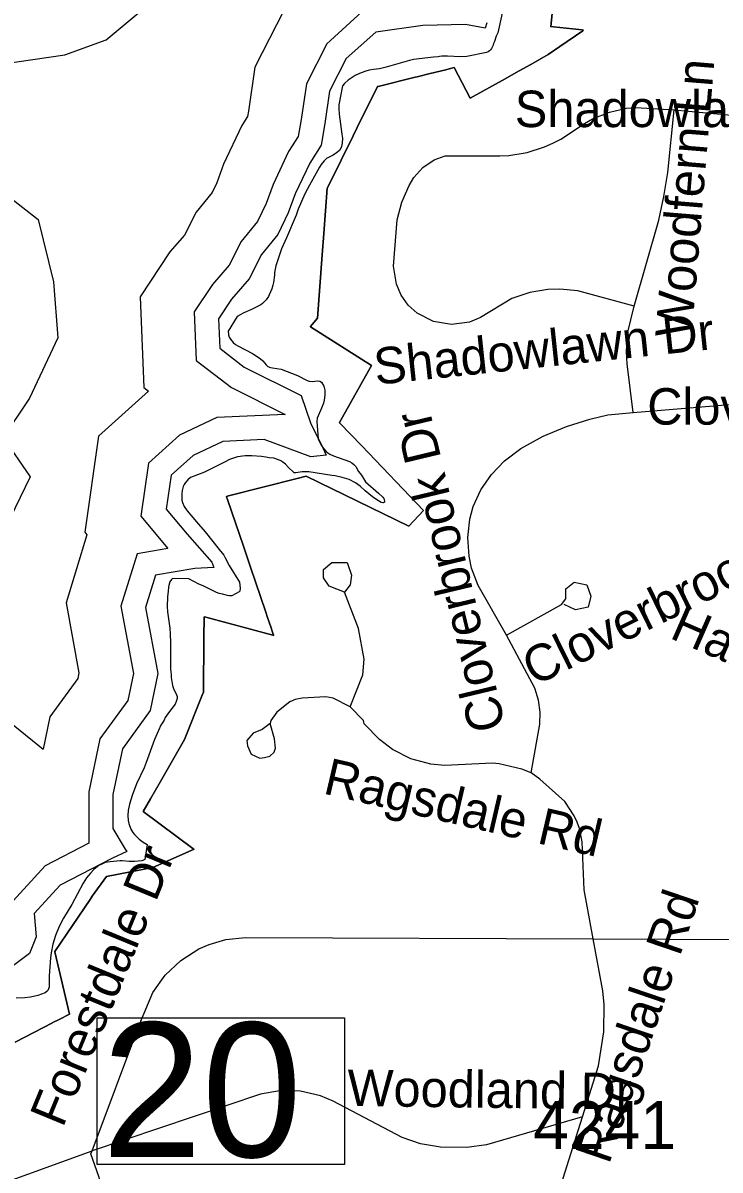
# Model space of a CAD drawing. Extents: x 1662474 to 1856135, y 779280 to 917889.
# Drawn here: x 1721124 to 1722940, y 819694 to 822681 of the extents above; entities that cross this region are included whole.
import ezdxf

# ---------------------------------------------------------------- set-up
doc = ezdxf.new("R2010")
doc.units = 0
for name, color, linetype in [('Exist Boundary Political City Limit New', 7, 'Continuous'), ('Exist Hydrographic Buffer Line', 7, 'Continuous'), ('Exist Hydrographic Lake Shore', 7, 'Continuous'), ('Exist Road Non-System Type 51', 7, 'Continuous'), ('Exist Road Non-System Type 51 Label', 7, 'Continuous'), ('Exist Road Secondary Structure Standard Bridge Number Label', 7, 'Continuous'), ('Exist Road Secondary Type 51 Number Label', 7, 'Continuous'), ('Map Preparation Boundary City Limit Buffer Line', 7, 'Continuous')]:
    doc.layers.add(name, color=color, linetype=linetype)

msp = doc.modelspace()

# ---------------------------------------------------------------- linework, layer by layer
at = {"layer": 'Exist Boundary Political City Limit New'}
for points in [[(1722511.6, 822791.3), (1722499.1, 822672.2), (1722499, 822671.6), (1722506.8, 822670.7), (1722556, 822665.6), (1722581, 822663), (1722584.5, 822662.3), (1722582.4, 822660.8), (1722523, 822619.5), (1722492.9, 822598.5), (1722447, 822572.9), (1722445.4, 822572), (1722409.2, 822551.9), (1722380.8, 822535.8), (1722289.6, 822484.8), (1722248.1, 822564.9), (1722234.4, 822561.4), (1722226.4, 822559.4), (1722184.9, 822549.2), (1722151.6, 822541.1), (1722146.2, 822539.8), (1722049.6, 822515.9), (1722048.1, 822515.5), (1721995.4, 822409.1), (1721984.5, 822386.9), (1721921.8, 822260.1), (1721917.2, 822251.1), (1721908.2, 822133.2), (1721904, 822077), (1721891.6, 821912.6), (1721891.5, 821912), (1721877.5, 821895.4), (1721873.5, 821890.7), (1721873.5, 821890.1), (1722032.5, 821788.9), (1721948.9, 821640.5), (1721948.9, 821639.9), (1722006.8, 821579.7), (1722167.9, 821411.3), (1722129.6, 821370.7), (1721862.4, 821500.9), (1721838.6, 821494.8), (1721659.8, 821449.3), (1721654.5, 821447.9), (1721654.6, 821447.3), (1721657, 821440.2), (1721698.6, 821318.2), (1721718.1, 821261), (1721756, 821149.7), (1721758.8, 821141.7), (1721760.1, 821137.9), (1721767.6, 821115.3), (1721769, 821111.4), (1721775.5, 821092.4), (1721777, 821087.6), (1721777.2, 821086.1), (1721775.1, 821086.6), (1721600.6, 821133.8), (1721596.8, 821134.8), (1721596.8, 821134.2), (1721595.8, 821080), (1721595.8, 821079.3), (1721595.8, 821078.7), (1721594.4, 820939), (1721594.4, 820938.3), (1721591.4, 820930.8), (1721545.1, 820814.9), (1721482.5, 820705.7), (1721456.9, 820661), (1721438, 820627.4), (1721567.2, 820531.4), (1721569.8, 820529.6), (1721570.2, 820529.2), (1721462.9, 820481.6), (1721342.4, 820458.6), (1721305.2, 820406.8), (1721299.5, 820398.8), (1721207.8, 820262.8), (1721207.8, 820262.2), (1721246.2, 820099.6), (1721219, 820086.2), (1721202.1, 820078), (1721201.1, 820077.5), (1721103.9, 820027.2)], [(1721103.9, 820027.2), (1721201.1, 820077.5), (1721202.1, 820078), (1721219, 820086.2), (1721246.2, 820099.6), (1721207.8, 820262.2), (1721207.8, 820262.8), (1721299.5, 820398.8), (1721305.2, 820406.8), (1721342.4, 820458.6), (1721462.9, 820481.6), (1721570.2, 820529.2), (1721569.8, 820529.6), (1721567.2, 820531.4), (1721438, 820627.4), (1721456.9, 820661), (1721482.5, 820705.7), (1721545.1, 820814.9), (1721591.4, 820930.8), (1721594.4, 820938.3), (1721594.4, 820939), (1721595.8, 821078.7), (1721595.8, 821079.3), (1721595.8, 821080), (1721596.8, 821134.2), (1721596.8, 821134.8), (1721600.6, 821133.8), (1721775.1, 821086.6), (1721777.2, 821086.1), (1721777, 821087.6), (1721775.5, 821092.4), (1721769, 821111.4), (1721767.6, 821115.3), (1721760.1, 821137.9), (1721758.8, 821141.7), (1721756, 821149.7), (1721718.1, 821261), (1721698.6, 821318.2), (1721657, 821440.2), (1721654.6, 821447.3), (1721654.5, 821447.9), (1721659.8, 821449.3), (1721838.6, 821494.8), (1721862.4, 821500.9), (1722129.6, 821370.7), (1722167.9, 821411.3), (1722006.8, 821579.7), (1721948.9, 821639.9), (1721948.9, 821640.5), (1722032.5, 821788.9), (1721873.5, 821890.1), (1721873.5, 821890.7), (1721877.5, 821895.4), (1721891.5, 821912), (1721891.6, 821912.6), (1721904, 822077), (1721908.2, 822133.2), (1721917.2, 822251.1), (1721921.8, 822260.1), (1721984.5, 822386.9), (1721995.4, 822409.1), (1722048.1, 822515.5), (1722049.6, 822515.9), (1722146.2, 822539.8), (1722151.6, 822541.1), (1722184.9, 822549.2), (1722226.4, 822559.4), (1722234.4, 822561.4), (1722248.1, 822564.9), (1722289.6, 822484.8), (1722380.8, 822535.8), (1722409.2, 822551.9), (1722445.4, 822572), (1722447, 822572.9), (1722492.9, 822598.5), (1722523, 822619.5), (1722582.4, 822660.8), (1722584.5, 822662.3), (1722581, 822663), (1722556, 822665.6), (1722506.8, 822670.7), (1722499, 822671.6), (1722499.1, 822672.2), (1722511.6, 822791.3)]]:
    msp.add_lwpolyline(points, dxfattribs=at)
at = {"layer": 'Exist Hydrographic Buffer Line'}
for points in [[(1720878.8, 822799.1), (1720928.4, 822707), (1721067.2, 822573.5), (1721233.9, 822598.2), (1721341.6, 822636.9), (1721440.5, 822719.4), (1721516.4, 822729.2), (1721573.7, 822828.3), (1721581.1, 822830.8), (1721660.4, 822895), (1721735.3, 822993.1), (1721741.7, 823098.6), (1721742.4, 823104.9), (1721765.1, 823173.2), (1721740.6, 823345.2), (1721657.4, 823428.4)], [(1722006.9, 822710), (1721925.3, 822635), (1721916.3, 822627), (1721862.7, 822522.8), (1721849.3, 822429.4), (1721841.5, 822385.7), (1721816.5, 822346.4), (1721775.9, 822260.1), (1721757.9, 822210.5), (1721735.4, 822163.8), (1721692.8, 822112.2), (1721661.7, 822049.9), (1721617.9, 821999.9), (1721570.4, 821928.5), (1721575.9, 821802.3), (1721667.5, 821731.5), (1721807.8, 821661.8), (1721629.9, 821653.3), (1721532.5, 821607.9), (1721451.6, 821535), (1721431.8, 821396.6), (1721502.1, 821312.2), (1721421.6, 821298.8), (1721379.7, 821162.5), (1721412.3, 820987.4), (1721397.5, 820916.4), (1721325, 820816.6), (1721296.2, 820678.6), (1721296.2, 820544.8), (1721182.6, 820486), (1721089.1, 820384.6)], [(1721804.4, 822713.4), (1721728.3, 822565.6), (1721712, 822451.5), (1721709.4, 822437.2), (1721694.4, 822413.6), (1721647.3, 822313.5), (1721629.6, 822264.6), (1721617.4, 822239.3), (1721575.5, 822188.5), (1721545.2, 822128), (1721507.2, 822084.6), (1721429.4, 821967.8), (1721439.7, 821731.8), (1721451.8, 821722.4), (1721321, 821604.6), (1721285.4, 821355.1), (1721291.2, 821348), (1721236.7, 821170.7), (1721270.5, 820989), (1721267.4, 820974), (1721194.9, 820874.2), (1721177.4, 820790.3)], [(1722332.7, 822681.2), (1722328.5, 822667.7), (1722277.5, 822677), (1722166, 822674.6), (1722043.7, 822657.1), (1721966.7, 822588.1), (1721923.2, 822503.5), (1721911.2, 822419.5), (1721901, 822362.5), (1721871.5, 822316.2), (1721833.8, 822236), (1721815.7, 822186.2), (1721788.6, 822129.8), (1721745.6, 822077.8), (1721714.1, 822014.7), (1721667.8, 821961.7), (1721633.9, 821910.8), (1721637.2, 821834.1), (1721700.9, 821784.9), (1721849.6, 821711), (1721873.4, 821639.5), (1721905.9, 821574.5), (1721914.7, 821555.5), (1721874.5, 821551.4), (1721752.9, 821596.5), (1721645.2, 821591.4), (1721567.5, 821555.1), (1721510.4, 821503.6), (1721497.8, 821415.3), (1721552.2, 821350), (1721616.8, 821276.7), (1721622.1, 821262.9), (1721572.4, 821260.4), (1721470.1, 821243.4), (1721444.1, 821158.8), (1721476.1, 820986.8), (1721456.1, 820890.4), (1721383.5, 820790.6), (1721358.9, 820672.1), (1721358.9, 820583.2), (1721391.1, 820529.4), (1721395.3, 820523.6), (1721358, 820506.2), (1721221.2, 820435.4), (1721153.8, 820362.4), (1721158.9, 820301.5), (1721142, 820257.6), (1721075.5, 820208.6)], [(1720971.3, 822319.7), (1721164.2, 822169.1), (1721203.7, 822006.5), (1721215.5, 821861.1), (1721141.7, 821703.9), (1721073.4, 821601.3), (1721143.4, 821499.5), (1721026.4, 821258.8)], [(1720394, 820274.6), (1720352.6, 820398.7), (1720486.2, 820610.3), (1720608.6, 820652.7), (1720630.8, 820663.8), (1720663.9, 820750.3), (1720751.1, 820837.6), (1720861.6, 820888.6), (1721042.7, 820898.1), (1721177.4, 820790.3)]]:
    msp.add_lwpolyline(points, dxfattribs=at)
at = {"layer": 'Exist Hydrographic Lake Shore'}
for points in [[(1722372.5, 822706.1), (1722361, 822655.7), (1722357.2, 822646.8), (1722353.1, 822632.4), (1722350.5, 822627.6), (1722348.9, 822623.2), (1722344.5, 822614.5), (1722341.9, 822610.8), (1722339.5, 822608.2), (1722335.8, 822605.8), (1722331.9, 822604.2), (1722280.6, 822593.8), (1722264.1, 822593), (1722230.5, 822594.8), (1722215.2, 822594.8), (1722209.8, 822594), (1722205.9, 822592.7), (1722193.8, 822592.2), (1722142.1, 822585.6), (1722131, 822583.5), (1722106.9, 822576.7), (1722070.8, 822565.7), (1722053.1, 822562), (1722037.4, 822559.9), (1722026.6, 822557.8), (1722017.9, 822555.4), (1722005.4, 822551.5), (1721999, 822548.9)], [(1721999, 822548.9), (1721990.1, 822544.2), (1721971.5, 822532.4), (1721961.8, 822523.2), (1721957.2, 822517.6)], [(1721957.2, 822517.6), (1721947.1, 822467.5), (1721947.1, 822457.3), (1721948.4, 822443.4), (1721955.5, 822391.4), (1721956.5, 822380.6), (1721956.2, 822368.1), (1721954.4, 822359.4), (1721952.9, 822354.9), (1721948.9, 822348.9), (1721941.5, 822342.6), (1721932.9, 822336.8), (1721924, 822332.1), (1721915.2, 822328.1), (1721909.2, 822322.1), (1721901.6, 822312.4), (1721897.2, 822305.8), (1721870.8, 822258.3), (1721858.9, 822235.8), (1721841, 822195.9), (1721835.8, 822180.9), (1721810.9, 822121.1), (1721797.8, 822092.8), (1721782.8, 822048.4), (1721780.1, 822031.1), (1721779.9, 822024.5), (1721777.5, 822005.3), (1721775.6, 821998.2), (1721772.8, 821989.1), (1721766.2, 821973.1), (1721764.1, 821969.1), (1721758.4, 821960.4), (1721748.4, 821950.2), (1721744.5, 821947.1), (1721719.5, 821934.8), (1721700.1, 821926.6), (1721690.4, 821921.3), (1721682.8, 821916.4), (1721659.1, 821878.6), (1721660.2, 821868.6), (1721662, 821862.6), (1721664.9, 821857.3), (1721672.2, 821848.6), (1721678, 821843.9), (1721684.1, 821840.2), (1721722.4, 821820.3), (1721742.6, 821806.9), (1721749.4, 821801.1), (1721758.4, 821790.6), (1721762.5, 821786.7), (1721769.4, 821784.1), (1721774.4, 821783), (1721797.2, 821779.9), (1721839.5, 821762.8), (1721864.4, 821749.9), (1721870.4, 821747.9), (1721877.8, 821747.3), (1721892, 821749.4), (1721897.8, 821748.4), (1721902.5, 821745.2), (1721907.8, 821734.8), (1721910.4, 821724.5), (1721910.6, 821712.1), (1721909.5, 821698.8), (1721907.1, 821690.6), (1721902.5, 821678.3), (1721890.6, 821652.3), (1721889.6, 821643.4), (1721893.2, 821598.5), (1721897.8, 821588.2), (1721903.2, 821578.8), (1721908.5, 821571.8), (1721914.5, 821565.4), (1721919, 821561.5), (1721924, 821558.1), (1721933.6, 821553.4), (1721975.4, 821538.7), (1721980.9, 821535.8), (1721986.1, 821531.6), (1721991.4, 821525.8), (1721998.2, 821513.4), (1722006.6, 821503.2), (1722016.9, 821485.9), (1722051, 821456.2), (1722062.2, 821445.8), (1722064.4, 821442.3), (1722066, 821435.8), (1722065.8, 821433.4), (1722063.1, 821431.6), (1722061.5, 821431.6), (1722057.6, 821432.4), (1722043.9, 821441), (1722035, 821447.3), (1722015.6, 821462.6), (1722002.8, 821474.9), (1721997.2, 821479.4), (1721991.1, 821483.3), (1721974.4, 821491.9), (1721955.8, 821497.8), (1721938.1, 821501.9)], [(1721938.1, 821501.9), (1721929, 821502.4), (1721868.9, 821511.9), (1721852, 821512.4), (1721835, 821509.5), (1721831, 821509.8), (1721829, 821511.1), (1721816.1, 821523.4), (1721808.2, 821532.1), (1721801.6, 821537.4), (1721796.1, 821541), (1721790.4, 821543.6), (1721778, 821547.6), (1721765.8, 821548.4), (1721757, 821550.5), (1721746.2, 821552.3), (1721720.6, 821553.9), (1721703.5, 821553.6), (1721683.2, 821551), (1721662.2, 821544.2), (1721651.5, 821538.4), (1721597, 821511.1), (1721578.9, 821504.6), (1721561.2, 821497.2), (1721554.1, 821491.4), (1721547.9, 821484.6), (1721544.2, 821479.4), (1721541.9, 821474.1), (1721539.2, 821463.6), (1721538.1, 821454.7), (1721538.1, 821446.2), (1721538.6, 821438.4), (1721540, 821432.4), (1721544.8, 821422.1), (1721552.1, 821410.3), (1721561.8, 821399.1), (1721582, 821376.2), (1721598.8, 821356), (1721635.5, 821310.1), (1721647.4, 821294.8), (1721651.5, 821288.2), (1721661.8, 821268.1), (1721688.8, 821225), (1721690.4, 821209.2), (1721689.6, 821201.7), (1721687.8, 821199.3), (1721668.6, 821189.6), (1721666, 821188.8), (1721662.5, 821188.8), (1721657.2, 821189.9), (1721644.5, 821193.8), (1721635.5, 821195.4), (1721629, 821197.8), (1721593.5, 821215.1), (1721582.8, 821219.5), (1721556.5, 821233.9), (1721514.2, 821234.5), (1721511.6, 821232.1), (1721506.9, 821225.8), (1721504.2, 821216.1), (1721503.5, 821211.4), (1721502.8, 821201.1), (1721501.1, 821186.2), (1721500.4, 821161.2), (1721501.4, 821147.9), (1721507.1, 821104.8), (1721508.2, 821089.6), (1721509, 821068.1), (1721509.2, 820998.5), (1721510.4, 820984.6), (1721510.6, 820976.5), (1721512.8, 820961), (1721513.8, 820956), (1721516.9, 820947.9), (1721524.8, 820931.6), (1721526.1, 820926.9), (1721526.4, 820921.6), (1721524, 820913.8), (1721521.1, 820907.2), (1721503.2, 820884.9), (1721495.1, 820872), (1721492.5, 820865.2), (1721483.5, 820852.1), (1721477.2, 820838.4), (1721467.2, 820814.8), (1721445.8, 820755.5), (1721440, 820741.3), (1721420.6, 820699.8), (1721408.8, 820669.1), (1721401.9, 820646.8), (1721399, 820629.8), (1721398, 820616.9), (1721398.8, 820604.1), (1721400.4, 820596.2), (1721405.4, 820582), (1721410.6, 820572.6), (1721414.8, 820567.3), (1721427.6, 820555.5), (1721437.9, 820547.6), (1721447.9, 820541.8)], [(1721447.9, 820541.8), (1721441.9, 820502.8), (1721437.1, 820500.1), (1721434.2, 820499.1), (1721415.4, 820497.2), (1721400.9, 820497.2), (1721383.2, 820499.1), (1721377.5, 820499.3), (1721351.5, 820496.9), (1721338.6, 820494.6), (1721330, 820490.9), (1721322.4, 820487), (1721309, 820476.8), (1721300.4, 820467.3), (1721290.4, 820454.9), (1721281, 820441.3), (1721251.8, 820385.7), (1721230, 820350), (1721219, 820328.4), (1721209.2, 820304.8), (1721202.5, 820282.2), (1721198, 820259.4), (1721196.1, 820246.6), (1721193.2, 820199.9), (1721192.5, 820170.4), (1721189.4, 820161.8), (1721187.8, 820159.4), (1721182.5, 820155.2), (1721162.9, 820148.7), (1721144.5, 820143.9), (1721129, 820142.1), (1721106.9, 820141.8)]]:
    msp.add_lwpolyline(points, dxfattribs=at)
at = {"layer": 'Exist Road Non-System Type 51'}
for p, q in [((1722821.1, 822454.4), (1723200.4, 822420.2)), ((1722714.2, 821666.8), (1722996.1, 821689.9)), ((1722609.5, 820296.4), (1723144.1, 820293.5)), ((1720968.6, 819621.9), (1721304.9, 819743.9))]:
    msp.add_line(p, q, dxfattribs=at)
for points in [[(1722716.6, 821943.9), (1722569.6, 821983.2), (1722523.1, 821988), (1722491.4, 821986.9), (1722444.4, 821979.1), (1722398.2, 821963.4), (1722316.6, 821914), (1722287.5, 821902.2), (1722240.8, 821895.6), (1722193.8, 821903.8), (1722151.5, 821925), (1722128.1, 821946.2), (1722109.8, 821972), (1722097.1, 822000.9), (1722089.4, 822047.9), (1722099.2, 822168), (1722111.4, 822214.5), (1722130.2, 822257.8), (1722142.4, 822278.5), (1722165.9, 822304.8), (1722195.4, 822324.8), (1722223.9, 822334.9), (1722366.5, 822334.9), (1722390.4, 822336), (1722437.6, 822343.4), (1722483, 822358.1), (1722504.8, 822368), (1722525.8, 822378.5), (1722587.1, 822419.5), (1722608.4, 822431.2), (1722652.2, 822449.1), (1722696.9, 822458.9), (1722720.8, 822460.9), (1722821.1, 822454.4)], [(1722716.6, 821943.9), (1722780.4, 822167.8), (1722794.2, 822228.9), (1722803.8, 822291.9), (1722821.1, 822454.4)], [(1722714.2, 821666.8), (1722698.5, 821793), (1722696.9, 821824.8), (1722699.5, 821872), (1722716.6, 821943.9)], [(1722383.8, 821086.7), (1722310.4, 821215.9), (1722293.2, 821261.5), (1722286.4, 821292.4), (1722283.2, 821341), (1722288.8, 821388.8), (1722297.4, 821421.6), (1722317.4, 821465.2), (1722344.6, 821505.4), (1722379.1, 821541), (1722421.4, 821572.5), (1722479.6, 821604.8), (1722540.5, 821630.5), (1722601.4, 821649.4), (1722647.9, 821660.4), (1722714.2, 821666.8)], [(1721962, 821199.2), (1721921.9, 821214.2), (1721907.1, 821236), (1721907.1, 821258.1), (1721928.9, 821276.4), (1721969.4, 821276.4), (1721980.4, 821243.4), (1721976.4, 821217.9), (1721962, 821199.2)], [(1722383.8, 821086.7), (1722527.4, 821166.8), (1722538.1, 821181.2), (1722538.4, 821207.2), (1722560.1, 821225), (1722593.2, 821217.9), (1722604, 821188.5), (1722596.9, 821159.7), (1722563.9, 821152.4), (1722534.4, 821166.8)], [(1721976.8, 820900.1), (1722009.5, 820983.9), (1722013.1, 821024.2), (1721998.5, 821104.5), (1721962, 821199.2)], [(1722448.4, 820728.2), (1722470.4, 820854.7), (1722471.4, 820886.7), (1722467.2, 820917.9), (1722458.1, 820948.4), (1722383.8, 821086.7)], [(1721976.8, 820900.1), (1721932.1, 820922.4), (1721913.4, 820926.1), (1721851.8, 820922.4), (1721833.9, 820919.2), (1721819.8, 820913.2), (1721785.9, 820886.4), (1721770.4, 820864.4), (1721768.6, 820856.5)], [(1722448.4, 820728.2), (1722423.9, 820738.2), (1722365.1, 820751.5), (1722347.6, 820753.4), (1722222.6, 820747.1), (1722186.9, 820750.5), (1722135.2, 820765.2), (1722087.1, 820789.4), (1722053.1, 820814.8), (1722013.4, 820855.8), (1722011.4, 820864.7), (1721976.8, 820900.1)], [(1721768.6, 820856.5), (1721747.6, 820841.2), (1721724, 820831.4), (1721707.9, 820812.9), (1721709, 820798.5), (1721718.8, 820777), (1721741.2, 820766.5), (1721753.6, 820768.1), (1721767.5, 820772), (1721778.9, 820781.7), (1721782.2, 820792.2), (1721779.9, 820816.6), (1721768.6, 820856.5)], [(1722609.5, 820296.4), (1722586.6, 820424), (1722581.1, 820548.4), (1722574.4, 820583), (1722568.4, 820599.9), (1722560.1, 820616.6), (1722535.8, 820653.6), (1722471.1, 820712.2), (1722448.4, 820728.2)], [(1721304.9, 819743.9), (1721429.2, 820075.2), (1721463.1, 820156.5), (1721495.1, 820201.2), (1721535.5, 820239.4), (1721583, 820269.7), (1721609.2, 820281.4), (1721653.1, 820294.1), (1721704.2, 820299.9), (1722609.5, 820296.4)], [(1722581.9, 819832.7), (1722623.4, 819965.7), (1722637.6, 820053.7), (1722638.1, 820125.2), (1722635.2, 820161), (1722609.5, 820296.4)], [(1722581.9, 819832.7), (1722331.9, 819759.2), (1722280.6, 819752.4), (1722212.1, 819753.4), (1722160.4, 819762), (1722112.4, 819778.4), (1721932.1, 819873.1), (1721899.2, 819887.2), (1721847.1, 819899), (1721793, 819899.9), (1721743.1, 819891.2), (1721304.9, 819743.9)], [(1722529.8, 819394.9), (1722514.8, 819536.1), (1722515.9, 819588.9), (1722526.6, 819656.2), (1722581.9, 819832.7)], [(1721428.9, 819271.5), (1721427.4, 819304.6), (1721423.6, 819321.6), (1721322.6, 819677.5), (1721301.4, 819735.8), (1721304.9, 819743.9)]]:
    msp.add_lwpolyline(points, dxfattribs=at)
at = {"layer": 'Exist Road Secondary Structure Standard Bridge Number Label'}
msp.add_lwpolyline([(1721317.7, 820090.4), (1721961.9, 820090.4), (1721961.9, 819708), (1721317.7, 819708)], close=True, dxfattribs=at)
at = {"layer": 'Map Preparation Boundary City Limit Buffer Line'}
for points in [[(1722511.6, 822791.3), (1722499.1, 822672.2), (1722499, 822671.6), (1722506.8, 822670.7), (1722556, 822665.6), (1722581, 822663), (1722584.5, 822662.3), (1722582.4, 822660.8), (1722523, 822619.5), (1722492.9, 822598.5), (1722447, 822572.9), (1722445.4, 822572), (1722409.2, 822551.9), (1722380.8, 822535.8), (1722289.6, 822484.8), (1722248.1, 822564.9), (1722234.4, 822561.4), (1722226.4, 822559.4), (1722184.9, 822549.2), (1722151.6, 822541.1), (1722146.2, 822539.8), (1722049.6, 822515.9), (1722048.1, 822515.5), (1721995.4, 822409.1), (1721984.5, 822386.9), (1721921.8, 822260.1), (1721917.2, 822251.1), (1721908.2, 822133.2), (1721904, 822077), (1721891.6, 821912.6), (1721891.5, 821912), (1721877.5, 821895.4), (1721873.5, 821890.7), (1721873.5, 821890.1), (1722032.5, 821788.9), (1721948.9, 821640.5), (1721948.9, 821639.9), (1722006.8, 821579.7), (1722167.9, 821411.3), (1722129.6, 821370.7), (1721862.4, 821500.9), (1721838.6, 821494.8), (1721659.8, 821449.3), (1721654.5, 821447.9), (1721654.6, 821447.3), (1721657, 821440.2), (1721698.6, 821318.2), (1721718.1, 821261), (1721756, 821149.7), (1721758.8, 821141.7), (1721760.1, 821137.9), (1721767.6, 821115.3), (1721769, 821111.4), (1721775.5, 821092.4), (1721777, 821087.6), (1721777.2, 821086.1), (1721775.1, 821086.6), (1721600.6, 821133.8), (1721596.8, 821134.8), (1721596.8, 821134.2), (1721595.8, 821080), (1721595.8, 821079.3), (1721595.8, 821078.7), (1721594.4, 820939), (1721594.4, 820938.3), (1721591.4, 820930.8), (1721545.1, 820814.9), (1721482.5, 820705.7), (1721456.9, 820661), (1721438, 820627.4), (1721567.2, 820531.4), (1721569.8, 820529.6), (1721570.2, 820529.2), (1721462.9, 820481.6), (1721342.4, 820458.6), (1721305.2, 820406.8), (1721299.5, 820398.8), (1721207.8, 820262.8), (1721207.8, 820262.2), (1721246.2, 820099.6), (1721219, 820086.2), (1721202.1, 820078), (1721201.1, 820077.5), (1721103.9, 820027.2)], [(1721103.9, 820027.2), (1721201.1, 820077.5), (1721202.1, 820078), (1721219, 820086.2), (1721246.2, 820099.6), (1721207.8, 820262.2), (1721207.8, 820262.8), (1721299.5, 820398.8), (1721305.2, 820406.8), (1721342.4, 820458.6), (1721462.9, 820481.6), (1721570.2, 820529.2), (1721569.8, 820529.6), (1721567.2, 820531.4), (1721438, 820627.4), (1721456.9, 820661), (1721482.5, 820705.7), (1721545.1, 820814.9), (1721591.4, 820930.8), (1721594.4, 820938.3), (1721594.4, 820939), (1721595.8, 821078.7), (1721595.8, 821079.3), (1721595.8, 821080), (1721596.8, 821134.2), (1721596.8, 821134.8), (1721600.6, 821133.8), (1721775.1, 821086.6), (1721777.2, 821086.1), (1721777, 821087.6), (1721775.5, 821092.4), (1721769, 821111.4), (1721767.6, 821115.3), (1721760.1, 821137.9), (1721758.8, 821141.7), (1721756, 821149.7), (1721718.1, 821261), (1721698.6, 821318.2), (1721657, 821440.2), (1721654.6, 821447.3), (1721654.5, 821447.9), (1721659.8, 821449.3), (1721838.6, 821494.8), (1721862.4, 821500.9), (1722129.6, 821370.7), (1722167.9, 821411.3), (1722006.8, 821579.7), (1721948.9, 821639.9), (1721948.9, 821640.5), (1722032.5, 821788.9), (1721873.5, 821890.1), (1721873.5, 821890.7), (1721877.5, 821895.4), (1721891.5, 821912), (1721891.6, 821912.6), (1721904, 822077), (1721908.2, 822133.2), (1721917.2, 822251.1), (1721921.8, 822260.1), (1721984.5, 822386.9), (1721995.4, 822409.1), (1722048.1, 822515.5), (1722049.6, 822515.9), (1722146.2, 822539.8), (1722151.6, 822541.1), (1722184.9, 822549.2), (1722226.4, 822559.4), (1722234.4, 822561.4), (1722248.1, 822564.9), (1722289.6, 822484.8), (1722380.8, 822535.8), (1722409.2, 822551.9), (1722445.4, 822572), (1722447, 822572.9), (1722492.9, 822598.5), (1722523, 822619.5), (1722582.4, 822660.8), (1722584.5, 822662.3), (1722581, 822663), (1722556, 822665.6), (1722506.8, 822670.7), (1722499, 822671.6), (1722499.1, 822672.2), (1722511.6, 822791.3)]]:
    msp.add_lwpolyline(points, dxfattribs=at)

# ---------------------------------------------------------------- texts
at = {"layer": 'Exist Road Non-System Type 51 Label'}
for s, rotation, p in [('Woodfern Ln', 85.304, (1722866, 821858.4)), ('Shadowlawn Dr', 6.0389, (1722043.7, 821738.6)), ('Cloverbrook Dr', 103.4829, (1722382.3, 820847.5)), ('Cloverbrook Ct', 26.2202, (1722456.3, 820953.1)), ('Hamlin Ct', 336.3587, (1722805.9, 821080.4)), ('Ragsdale Rd', 346.9376, (1721903.5, 820675.1)), ('Forestdale Dr', 67.6313, (1721228.2, 819801.9)), ('Ragsdale Rd', 71.1852, (1722650.7, 819706.4)), ('Woodland Dr', 359.2668, (1721969.2, 819860.8))]:
    msp.add_text(s, height=95, rotation=rotation, dxfattribs=at).set_placement(p)
for s, p in [('Shadowlawn Dr', (1722405.5, 822409.8)), ('Cloverbrook Dr', (1722750.7, 821635))]:
    msp.add_text(s, height=95, dxfattribs=at).set_placement(p)
at = {"layer": 'Exist Road Secondary Structure Standard Bridge Number Label'}
msp.add_text('20', height=350, dxfattribs=at).set_placement((1721330.3, 819727.8))
at = {"layer": 'Exist Road Secondary Type 51 Number Label'}
msp.add_text('4241', height=125, dxfattribs=at).set_placement((1722453.6, 819748.4))

doc.saveas('drawing.dxf')
